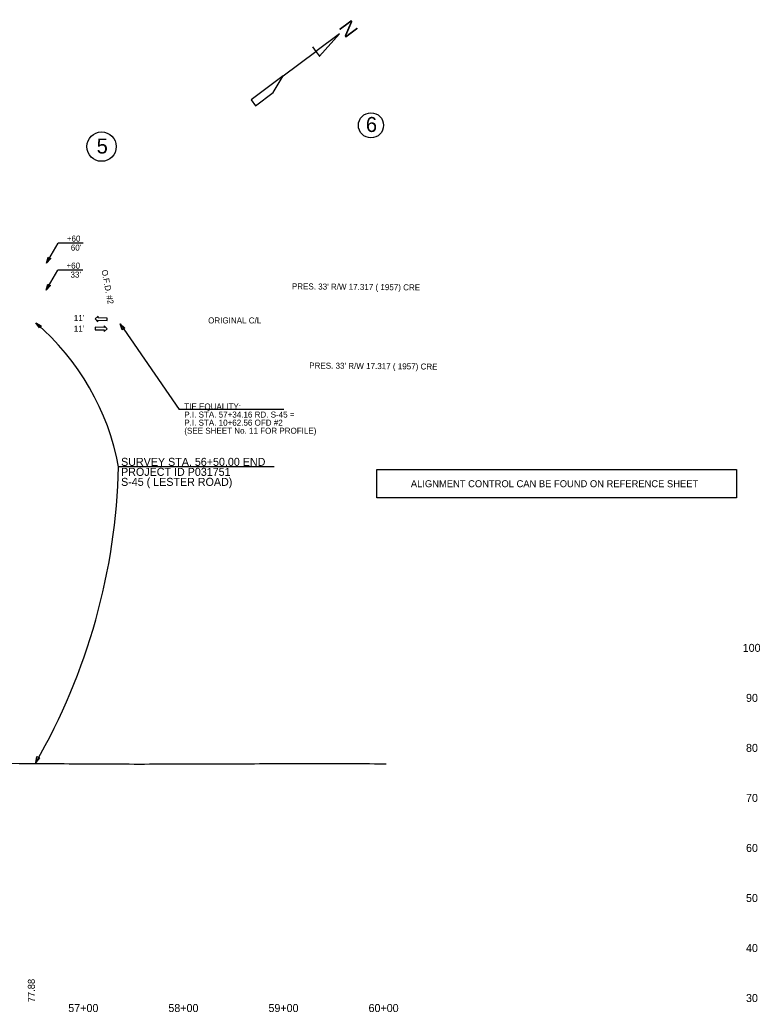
# Model space of a CAD drawing. Extents: x -3336 to 3318, y -3606 to 6276.
# Drawn here: x 834 to 1574, y 641 to 1633 of the extents above; entities that cross this region are included whole.
import ezdxf

# ---------------------------------------------------------------- set-up
doc = ezdxf.new("R2010")
doc.units = 0
for name, color, linetype in [('RD_DDB_ElevTX', 7, 'Continuous'), ('RD_DDB_Profile_EX', 7, 'Continuous'), ('RD_DDB_Profile_PR', 7, 'Continuous'), ('RD_DDB_StaTX', 7, 'Continuous'), ('RD_DDB_StripGrade', 7, 'Continuous'), ('RD_EX_DV_TX_Prop', 7, 'Continuous'), ('RD_EX_Misc', 7, 'Continuous'), ('RD_EX_RW_TX', 7, 'Continuous'), ('RD_HC_Data', 7, 'Continuous'), ('RD_PD_Driveway_TX', 7, 'Continuous'), ('RD_PD_Final_LnLine', 7, 'Continuous'), ('RD_PD_Final_TX', 7, 'Continuous'), ('RD_PD_RW', 7, 'Continuous'), ('RD_Sketch1', 7, 'Continuous'), ('RD_TX_Drainage', 7, 'Continuous'), ('RD_TX_RoadID', 7, 'Continuous')]:
    doc.layers.add(name, color=color, linetype=linetype)

msp = doc.modelspace()

# ---------------------------------------------------------------- linework, layer by layer
at = {"layer": 'RD_DDB_Profile_EX'}
for points in [[(833.38, 889.38), (838.38, 889.39), (843.38, 889.39), (848.38, 889.4), (853.38, 889.38), (858.38, 889.36), (863.38, 889.34), (868.38, 889.31), (873.38, 889.29), (878.38, 889.25), (883.38, 889.23), (888.38, 889.2), (893.38, 889.18), (898.38, 889.15), (903.38, 889.13), (908.38, 889.1), (913.38, 889.08), (918.38, 889.05), (923.38, 889.03), (928.38, 888.99), (933.38, 888.97), (938.38, 888.94), (943.38, 888.92), (948.38, 888.89), (953.38, 888.89), (958.38, 888.91), (963.38, 888.93), (968.38, 888.95), (973.38, 888.97), (978.38, 889), (983.38, 889.02), (988.38, 889.04), (993.38, 889.05), (998.38, 889.07)], [(998.38, 889.07), (1003.38, 889.09), (1008.38, 889.11), (1013.38, 889.13), (1018.38, 889.15), (1023.38, 889.15), (1028.38, 889.16), (1033.38, 889.17), (1038.38, 889.18), (1043.38, 889.18), (1048.38, 889.19), (1053.38, 889.2), (1058.38, 889.21), (1063.38, 889.23), (1068.38, 889.24), (1073.38, 889.25), (1078.38, 889.27), (1083.38, 889.28), (1088.38, 889.3), (1093.38, 889.31), (1098.38, 889.32), (1103.38, 889.34), (1108.38, 889.35), (1113.38, 889.37), (1118.38, 889.38), (1123.38, 889.39), (1128.38, 889.41), (1133.38, 889.43), (1138.38, 889.44), (1143.38, 889.45), (1148.38, 889.47), (1153.38, 889.48), (1158.38, 889.47), (1163.38, 889.43), (1168.38, 889.4), (1173.38, 889.36), (1178.38, 889.32), (1183.38, 889.28), (1188.38, 889.24), (1193.38, 889.2), (1198.38, 889.17), (1200, 889.15)]]:
    msp.add_lwpolyline(points, dxfattribs=at)
at = {"layer": 'RD_DDB_Profile_PR'}
msp.add_line((825, 889.69), (850, 889.4), dxfattribs=at)
at = {"layer": 'RD_EX_DV_TX_Prop'}
for centre, radius in [((1184.83, 1527.25), 12.57), ((915.67, 1505.98), 14.69)]:
    msp.add_circle(centre, radius, dxfattribs=at)
at = {"layer": 'RD_EX_Misc'}
for p, q in [((1153.36, 1618.63), (1129.79, 1601.05)), ((1133.3, 1596.34), (1153.36, 1618.63)), ((1153.36, 1618.63), (1153.36, 1618.63)), ((1097.08, 1576.66), (1129.79, 1601.05)), ((1126.27, 1605.76), (1129.79, 1601.05)), ((1129.79, 1601.05), (1133.3, 1596.34)), ((1133.3, 1596.34), (1133.58, 1596.54)), ((1097.08, 1576.66), (1064.97, 1552.71)), ((1087.05, 1560), (1097.08, 1576.66)), ((1069.37, 1546.82), (1087.21, 1560.13)), ((1087.21, 1560.13), (1087.05, 1560)), ((1064.97, 1552.71), (1069.37, 1546.82))]:
    msp.add_line(p, q, dxfattribs=at)
at = {"layer": 'RD_HC_Data'}
for p in [(934.1, 1328.75), (1097.79, 1243.24)]:
    msp.add_line(p, (993.32, 1243.24), dxfattribs=at)
at = {"layer": 'RD_PD_Final_LnLine'}
for points in [[(921.18, 1332.12), (921.29, 1334.51), (912.12, 1334.92), (912.19, 1336.54), (909.24, 1333.84), (911.95, 1330.89), (912.02, 1332.52)], [(909.21, 1325.37), (909.17, 1322.97), (918.34, 1322.8), (918.31, 1321.17), (921.19, 1323.94), (918.41, 1326.82), (918.38, 1325.2)]]:
    msp.add_lwpolyline(points, close=True, dxfattribs=at)
at = {"layer": 'RD_PD_Final_TX'}
msp.add_line((1088.08, 1185.91), (932.64, 1185.91), dxfattribs=at)
for centre, radius, start, end in [((688.41, 1141.19), 248.29, 10.37551, 49.41659), ((309.46, 1200.72), 623.36, 330.12774, 358.63781)]:
    msp.add_arc(centre, radius, start, end, dxfattribs=at)
at = {"layer": 'RD_PD_RW'}
for p, q in [((860.66, 1389.63), (872.43, 1409.56)), ((897.11, 1409.56), (872.43, 1409.56)), ((860.33, 1362.63), (872.11, 1382.56)), ((896.78, 1382.56), (872.11, 1382.56))]:
    msp.add_line(p, q, dxfattribs=at)
at = {"layer": 'RD_Sketch1'}
msp.add_lwpolyline([(1190.84, 1183.25), (1550, 1183.25), (1550, 1154.86), (1190.84, 1154.86)], close=True, dxfattribs=at)
at = {"layer": 'RD_TX_Drainage'}
for points in [[(865, 1394.03), (860.66, 1389.63), (862.42, 1395.56)], [(864.68, 1367.04), (860.33, 1362.63), (862.09, 1368.56)], [(853.5, 1324.7), (849.94, 1329.76), (855.46, 1326.97)], [(936.28, 1322.96), (934.1, 1328.75), (938.75, 1324.67)], [(853.73, 895.19), (850, 890.25), (850.96, 896.36)]]:
    msp.add_lwpolyline(points, close=True, dxfattribs=at)

# ---------------------------------------------------------------- texts
at = {"layer": 'RD_DDB_ElevTX'}
for s, p in [('100', (1556.24, 1001)), ('90', (1559.54, 951)), ('80', (1559.54, 901)), ('70', (1559.54, 851)), ('60', (1559.54, 801)), ('50', (1559.54, 751)), ('40', (1559.54, 701)), ('30', (1559.54, 651))]:
    msp.add_text(s, height=8, dxfattribs=at).set_placement(p)
at = {"layer": 'RD_DDB_StaTX'}
for s, p in [('57+00', (882.41, 641)), ('58+00', (982.41, 641)), ('59+00', (1082.41, 641)), ('60+00', (1182.41, 641))]:
    msp.add_text(s, height=8, dxfattribs=at).set_placement(p)
at = {"layer": 'RD_DDB_StripGrade'}
msp.add_text('77.88', height=7, rotation=90, dxfattribs=at).set_placement((849, 650.75))
at = {"layer": 'RD_EX_DV_TX_Prop'}
for s, p in [('6', (1179.71, 1520.6)), ('5', (910.77, 1499.06))]:
    msp.add_text(s, height=15, dxfattribs=at).set_placement(p)
at = {"layer": 'RD_EX_Misc'}
msp.add_text('N', height=15, rotation=306.71513, dxfattribs=at).set_placement((1152.05, 1625.03))
at = {"layer": 'RD_EX_RW_TX'}
for p in [(1105.76, 1363.38), (1123.12, 1284.23)]:
    msp.add_text("PRES. 33' R/W 17.317 ( 1957) CRE", height=6, rotation=359.47622, dxfattribs=at).set_placement(p)
at = {"layer": 'RD_HC_Data'}
for s, p in [('TIE EQUALITY:', (998.32, 1243.24)), ('P.I. STA. 57+34.16 RD. S-45 =', (998.32, 1235.16)), ('P.I. STA. 10+62.56 OFD #2', (998.32, 1227.08)), ('(SEE SHEET No. 11 FOR PROFILE)', (998.32, 1218.99))]:
    msp.add_text(s, height=6, dxfattribs=at).set_placement(p)
at = {"layer": 'RD_PD_Driveway_TX'}
for p in [(887.91, 1331.67), (887.91, 1321.02)]:
    msp.add_text("11'", height=6, dxfattribs=at).set_placement(p)
at = {"layer": 'RD_PD_Final_TX'}
for s, p in [('SURVEY STA. 56+50.00 END', (935.14, 1186.91)), ('PROJECT ID P031751', (935.14, 1176.91)), ('S-45 ( LESTER ROAD)', (935.14, 1166.91))]:
    msp.add_text(s, height=8, dxfattribs=at).set_placement(p)
at = {"layer": 'RD_PD_RW'}
for s, p in [('+60', (880.9, 1411.06)), ("  60'", (880.48, 1402.06)), ('+60', (880.58, 1384.06)), ("  33'", (880.15, 1375.06))]:
    msp.add_text(s, height=6, dxfattribs=at).set_placement(p)
at = {"layer": 'RD_Sketch1'}
msp.add_text('ALIGNMENT CONTROL CAN BE FOUND ON REFERENCE SHEET', height=7, dxfattribs=at).set_placement((1224.68, 1165.55))
at = {"layer": 'RD_TX_RoadID'}
msp.add_text('O.F.D. #2', height=6, rotation=280.72824, dxfattribs=at).set_placement((915.55, 1382.25))
msp.add_text('ORIGINAL C/L', height=6, dxfattribs=at).set_placement((1022.12, 1329.24))

doc.saveas('drawing.dxf')
